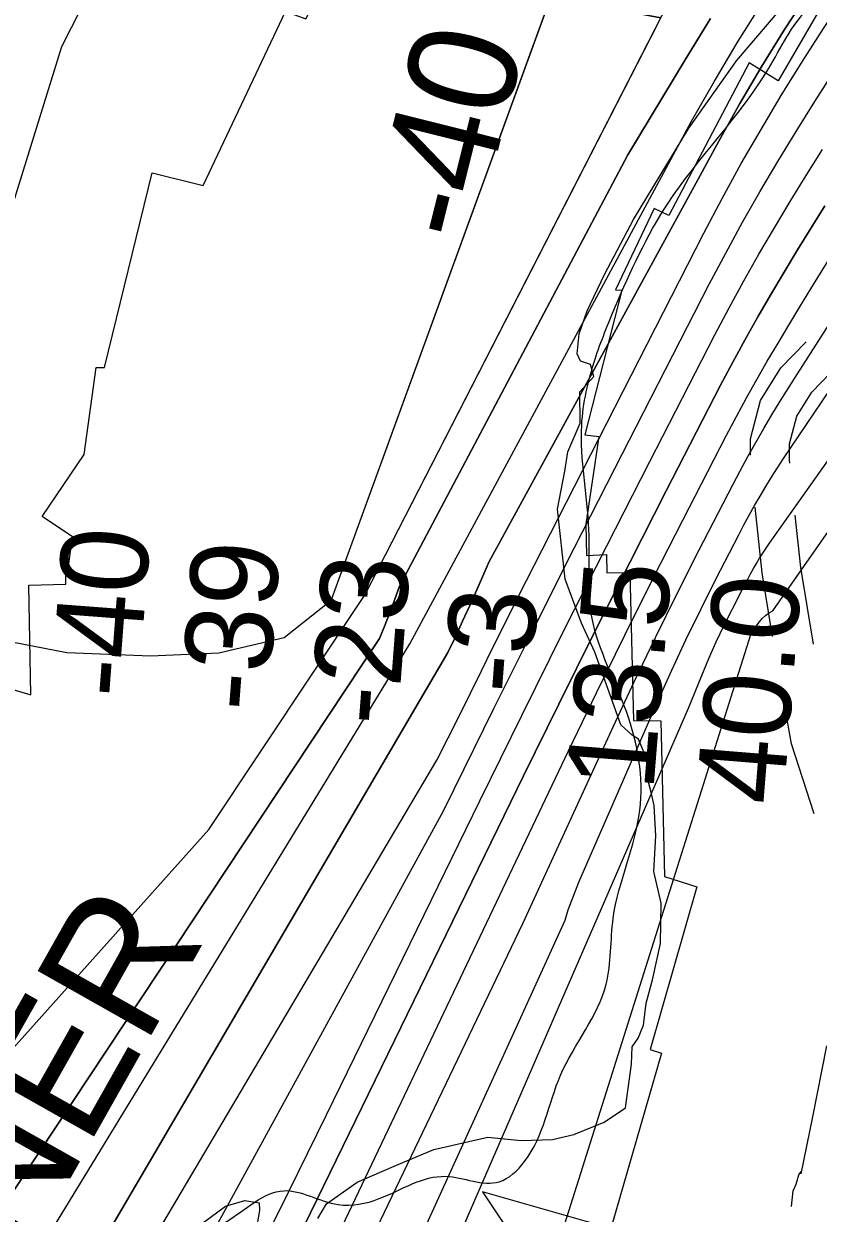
# Model space of a CAD drawing. Extents: x 3271442 to 3309282, y 752266 to 777610.
# Drawn here: x 3288016 to 3288625, y 760687 to 761598 of the extents above; entities that cross this region are included whole.
import ezdxf

# ---------------------------------------------------------------- set-up
doc = ezdxf.new("R2010")
doc.units = 0
for name, color, linetype in [('V-RIVR-EDGE', 7, 'Continuous'), ('V-RIVR-RANG', 7, 'Continuous'), ('V-ROAD-CNTR', 7, 'Continuous'), ('V-RRAP-FSHR', 7, 'Continuous'), ('V-RRAP-RVMT', 7, 'Continuous'), ('V-RRAP-RVMT-IDEN', 7, 'Continuous'), ('V-TOPO-DPTH', 7, 'Continuous'), ('V-TOPO-MAJR', 7, 'Continuous'), ('V-TOPO-MINR', 7, 'Continuous'), ('V-TOPO-MINR-IDEN', 7, 'Continuous'), ('V-TOPO-WATR', 7, 'Continuous')]:
    doc.layers.add(name, color=color, linetype=linetype)

msp = doc.modelspace()

# ---------------------------------------------------------------- linework, layer by layer
at = {"layer": 'V-RIVR-EDGE'}
for points in [[(3288447.55, 761378.15), (3288460.66, 761405.94), (3288482.93, 761448.04), (3288525.27, 761517.92), (3288561.91, 761569.56), (3288609.43, 761625.52)], [(3288241.1, 760682.74), (3288247.65, 760694.02), (3288271.16, 760710.48), (3288301.19, 760723.45), (3288329.9, 760735.55), (3288371.22, 760745.01), (3288396.86, 760742.34), (3288420.77, 760743.15), (3288437.3, 760747.02), (3288460.36, 760756.53), (3288476.9, 760767.35), (3288481.33, 760800.81), (3288481.8, 760814.29), (3288486.6, 760820.79), (3288490.54, 760830.78), (3288492.75, 760847.73), (3288497.58, 760865.54), (3288503.73, 760893.34), (3288504.24, 760924.2), (3288498.65, 760948.56), (3288500.02, 760975.94), (3288498.78, 760998.98), (3288496.2, 761010.29), (3288493.61, 761019.86), (3288494.08, 761032.03), (3288486.73, 761049.87), (3288481.96, 761052.92), (3288473.28, 761060.77), (3288453.43, 761116.46), (3288443.05, 761138.65), (3288430.53, 761172.59), (3288424.57, 761226.07), (3288430.3, 761255.18), (3288432.51, 761269.95), (3288442.12, 761292.1), (3288441.75, 761316), (3288452.64, 761327.71), (3288450.06, 761336.85), (3288442.24, 761339.48), (3288439.65, 761345.13), (3288441.42, 761360.34), (3288447.55, 761378.15)], [(3288130.21, 760662.58), (3288170.27, 760692.04), (3288185.06, 760696.35), (3288195.92, 760694.59), (3288196.34, 760688.93), (3288192.81, 760668.51)]]:
    msp.add_lwpolyline(points, dxfattribs=at)
at = {"layer": 'V-ROAD-CNTR'}
for points in [[(3288572.54, 761267.49), (3288572.59, 761280), (3288580.22, 761309.33), (3288595.95, 761334.35), (3288615.18, 761354.2)], [(3288602.75, 761261.37), (3288602.52, 761263.53), (3288602.58, 761276.1), (3288608.09, 761297.29), (3288619.68, 761315.73), (3288648.61, 761345.59)], [(3288589.61, 761128.64), (3288581.48, 761177.34), (3288576.15, 761227.68)], [(3288621.03, 761122.63), (3288611.22, 761181.39), (3288606.96, 761221.59)], [(3288621.34, 760992.61), (3288604.1, 761046.35), (3288596.29, 761089.2)], [(3288611.41, 760716.82), (3288620.42, 760760.57), (3288631.06, 760814.87)], [(3288604.06, 760691.85), (3288605.21, 760703.88), (3288607.53, 760709.03), (3288608.4, 760711.59), (3288609.74, 760716.2), (3288611.37, 760718.69)]]:
    msp.add_lwpolyline(points, dxfattribs=at)
at = {"layer": 'V-RRAP-FSHR'}
msp.add_spline([(3288024.63, 760323.97), (3288039.3, 760373.12), (3288065.44, 760447.36), (3288088.5, 760530.02), (3288126.81, 760603.55), (3288137.93, 760646.78), (3288150.99, 760667.86), (3288170.61, 760680.17), (3288214.86, 760704), (3288256.53, 760693.32), (3288288.02, 760697.88), (3288338.99, 760715), (3288379.97, 760710.81), (3288399.44, 760726.31), (3288427.1, 760792.56), (3288462.02, 760862.23), (3288467.43, 760912.73), (3288487.79, 760995.52), (3288477.56, 761070.97), (3288451.29, 761142.34), (3288448.83, 761210.37), (3288443.25, 761290.39), (3288453.5, 761340.99), (3288468.99, 761381.1), (3288508.98, 761459.84), (3288586.39, 761563.48), (3288616.8, 761609.67), (3288678.43, 761644.56), (3288740.06, 761679.44), (3288795.46, 761719.02), (3288838.61, 761790.36), (3288890.24, 761863.5)], degree=3, dxfattribs=at)
at = {"layer": 'V-RRAP-RVMT'}
for points in [[(3288047.91, 761168.75), (3288047.63, 761183.56), (3288050.01, 761184.17), (3288052.93, 761204.97), (3288029.62, 761220.55), (3288061.78, 761268.08), (3288071.12, 761334.61), (3288077.38, 761334.68), (3288113.96, 761483.64), (3288153.2, 761474.08), (3288216.08, 761607.39), (3288231.66, 761601.64), (3288299.01, 761732.39), (3288303.07, 761730.39), (3288378.07, 761859.59), (3288404.93, 761842.28), (3288478.05, 761968.95), (3288490.91, 761961.39), (3288564.39, 762088.36), (3288581.34, 762077.72), (3288654.82, 762203.99)], [(3289090.33, 762108.87), (3289016.46, 761984.19), (3288991.86, 761997.73), (3288977.5, 761981.67), (3288914.59, 761873.35), (3288889.01, 761888.63), (3288815.29, 761762.18), (3288792.96, 761775.53), (3288720.4, 761650.05), (3288666.66, 761679.67), (3288593.77, 761554.36), (3288571.56, 761568.06), (3288510.09, 761451.04), (3288498.72, 761456.41), (3288469.1, 761394.2), (3288473.95, 761394), (3288445.57, 761283.02), (3288456.34, 761281.88), (3288446.51, 761214.53), (3288446.97, 761190.48), (3288462.2, 761191.44), (3288462.46, 761177.3)], [(3288462.46, 761177.3), (3288480.11, 761177.51), (3288482.87, 761064.13), (3288503.81, 761064), (3288506.71, 760944.59), (3288531.46, 760936.86), (3288495.73, 760812.05), (3288504.42, 760809.36), (3288465.59, 760675.1), (3288367.13, 760703.2), (3288410.28, 760638.16)], [(3287405.23, 759886.02), (3287443.57, 760020.81), (3287460.11, 760016.42), (3287494.03, 760134.84), (3287492.61, 760135.21), (3287530.39, 760269.65), (3287551.7, 760263.93), (3287587.78, 760391.62), (3287592.82, 760390.19), (3287628.55, 760516.3), (3287648.53, 760510.74), (3287685, 760638.05), (3287782.33, 760610.6), (3287818.27, 760735.36), (3287841.66, 760728.59), (3287877.58, 760854.27), (3287882.41, 760853.2), (3287917.79, 760976.97), (3287953.93, 760967.05), (3287989.71, 761092.96), (3288021.11, 761083.88), (3288019.36, 761167.95), (3288047.91, 761168.75)]]:
    msp.add_lwpolyline(points, dxfattribs=at)
at = {"layer": 'V-TOPO-DPTH'}
for p, q in [((3288629.55, 761458.53), (3288619.09, 761441.64)), ((3288619.09, 761441.64), (3288608.7, 761424.71)), ((3288608.7, 761424.71), (3288598.43, 761407.7)), ((3288598.43, 761407.7), (3288588.23, 761390.65)), ((3288588.23, 761390.65), (3288578.25, 761373.47)), ((3288578.25, 761373.47), (3288568.48, 761356.18)), ((3288568.48, 761356.18), (3288559.02, 761338.72)), ((3288559.02, 761338.72), (3288549.76, 761321.14)), ((3288549.76, 761321.14), (3288508.08, 761240.22)), ((3288508.08, 761240.22), (3288480.3, 761185.85)), ((3288480.3, 761185.85), (3288452.76, 761131.37)), ((3288452.76, 761131.37), (3288425.59, 761076.7)), ((3288425.59, 761076.7), (3288398.66, 761021.91))]:
    msp.add_line(p, q, dxfattribs=at)
for points in [[(3287738.29, 760512.96), (3288157.38, 760980.59), (3288277.25, 761160.7), (3288623.48, 761835.79), (3288633.92, 761851.98), (3288644.26, 761868.24), (3289076.32, 762359.08)], [(3287924.79, 761194.92), (3288044.85, 761580.52), (3288154.96, 761797.02), (3288250.46, 761887.3), (3288286.32, 761937.24), (3288384.36, 762089.45), (3288463.32, 762232.18), (3288501.5, 762258.28), (3288522.94, 762258.23), (3288549.12, 762248.64), (3288563.33, 762217.64), (3288567.95, 762160.45), (3288529.25, 761922.34), (3288507.66, 761860.46), (3288419.53, 761618.52), (3288503.81, 761602.46)], [(3288549.12, 762248.64), (3288563.33, 762217.64), (3288567.95, 762160.45), (3288529.25, 761922.34), (3288507.66, 761860.46), (3288251.04, 761156), (3288215.24, 761127.51), (3288165.18, 761115.72), (3288112.77, 761113.47), (3288048.46, 761116.01), (3287998.46, 761125.66), (3287955.6, 761132.91), (3287934.21, 761152.02), (3287924.79, 761194.92), (3288044.85, 761580.52), (3288154.96, 761797.02), (3288250.46, 761887.3), (3288286.32, 761937.24), (3288384.36, 762089.45), (3288463.32, 762232.18), (3288501.5, 762258.28), (3288522.94, 762258.23), (3288549.12, 762248.64)], [(3288092.9, 760548.2), (3288337.36, 760994.88), (3288345.58, 761011.67), (3288375.95, 761073.3), (3288406.55, 761134.8), (3288437.5, 761196.14), (3288468.69, 761257.35), (3288541.05, 761398.43), (3288553.61, 761422.27), (3288566.49, 761445.94), (3288579.88, 761469.32), (3288593.6, 761492.52), (3288607.68, 761515.51), (3288621.93, 761538.39), (3288636.42, 761561.12), (3288651.06, 761583.76), (3288782.4, 761784.41)], [(3288092.9, 760548.2), (3288337.36, 760994.88), (3288345.58, 761011.67), (3288375.95, 761073.3), (3288406.55, 761134.8), (3288437.5, 761196.14), (3288468.69, 761257.35), (3288541.05, 761398.43), (3288553.61, 761422.27), (3288566.49, 761445.94), (3288579.88, 761469.32), (3288593.6, 761492.52), (3288607.68, 761515.51), (3288621.93, 761538.39), (3288636.42, 761561.12), (3288651.06, 761583.76), (3288782.4, 761784.41)], [(3288051.29, 760622.7), (3288340.7, 761116.32), (3288346.39, 761128.25), (3288351.99, 761140.23), (3288357.43, 761152.28), (3288362.78, 761164.37), (3288370.66, 761182.53), (3288372.1, 761185.51), (3288373.68, 761188.41), (3288532.45, 761478.8), (3288548.23, 761507.97), (3288564.48, 761536.87), (3288581.41, 761565.38), (3288598.79, 761593.63), (3288616.74, 761621.52)], [(3288616.74, 761621.52), (3288598.79, 761593.63), (3288581.41, 761565.38), (3288564.48, 761536.87), (3288548.23, 761507.97), (3288532.45, 761478.8), (3288373.68, 761188.41), (3288372.1, 761185.51), (3288370.66, 761182.53), (3288362.78, 761164.37), (3288357.43, 761152.28), (3288351.99, 761140.23), (3288346.39, 761128.25), (3288340.7, 761116.32), (3288051.29, 760622.7)], [(3288501.25, 761597.47), (3288503.81, 761602.46), (3288419.53, 761618.52), (3288416.57, 761610.4), (3288251.04, 761156), (3288215.24, 761127.51), (3288165.18, 761115.72), (3288112.77, 761113.47), (3288048.46, 761116.01), (3287998.46, 761125.66)], [(3287737.65, 760511.18), (3287738.29, 760512.96), (3288157.38, 760980.59), (3288277.25, 761160.7), (3288501.25, 761597.47)], [(3288542.04, 761601.95), (3288522.55, 761570.32), (3288478.73, 761497.52), (3288303.46, 761167.2), (3288299.88, 761157.06), (3288296.18, 761146.96), (3288292.3, 761136.93), (3288288.31, 761126.95), (3287896.68, 760536.42)], [(3288542.04, 761601.95), (3288522.55, 761570.32), (3288478.73, 761497.52), (3288303.46, 761167.2), (3288299.88, 761157.06), (3288296.18, 761146.96), (3288292.3, 761136.93), (3288288.31, 761126.95), (3287896.68, 760536.42)], [(3288398.66, 761021.91), (3288156.23, 760524.49), (3288155.88, 760523.76)]]:
    msp.add_lwpolyline(points, dxfattribs=at)
at = {"layer": 'V-TOPO-MAJR'}
for p, q in [((3288598.04, 761264.83), (3288667.72, 761368.6)), ((3288588.8, 761250.63), (3288593.38, 761257.76)), ((3288593.38, 761257.76), (3288598.04, 761264.83)), ((3288584.36, 761243.43), (3288588.8, 761250.63)), ((3288580, 761236.17), (3288584.36, 761243.43)), ((3288571.61, 761221.45), (3288575.76, 761228.83)), ((3288575.76, 761228.83), (3288580, 761236.17)), ((3288567.59, 761214), (3288571.61, 761221.45)), ((3288563.64, 761206.51), (3288567.59, 761214)), ((3288546.07, 761172.39), (3288563.64, 761206.51)), ((3288534.46, 761149.32), (3288546.07, 761172.39)), ((3288523.14, 761126.11), (3288534.46, 761149.32)), ((3288512.27, 761102.68), (3288523.14, 761126.11)), ((3288501.69, 761079.12), (3288512.27, 761102.68)), ((3288441, 760940.34), (3288501.69, 761079.12)), ((3288432.98, 760919.15), (3288441, 760940.34)), ((3288430.57, 760911.19), (3288432.98, 760919.15))]:
    msp.add_line(p, q, dxfattribs=at)
msp.add_lwpolyline([(3288069.72, 759951.08), (3288256.63, 760529.5), (3288430.57, 760911.19)], dxfattribs=at)
at = {"layer": 'V-TOPO-MINR'}
for p, q in [((3288589.79, 761148.28), (3289028.4, 761776.55)), ((3288609.02, 761230.77), (3288989.32, 761770.72)), ((3288618.84, 761394.82), (3288848.48, 761768.93)), ((3288608.55, 761329.77), (3288749.37, 761549.64)), ((3288615.33, 761481.81), (3288627.75, 761501.72)), ((3288603.07, 761461.79), (3288615.33, 761481.81)), ((3288590.93, 761441.71), (3288603.07, 761461.79)), ((3288619.09, 761441.64), (3288629.55, 761458.53)), ((3288579.07, 761421.46), (3288590.93, 761441.71)), ((3288608.7, 761424.71), (3288619.09, 761441.64)), ((3288567.47, 761401.07), (3288579.07, 761421.46)), ((3288598.43, 761407.7), (3288608.7, 761424.71)), ((3288588.23, 761390.65), (3288598.43, 761407.7)), ((3288556.28, 761380.45), (3288567.47, 761401.07)), ((3288610.42, 761381.01), (3288618.84, 761394.82)), ((3288578.25, 761373.47), (3288588.23, 761390.65)), ((3288545.34, 761359.69), (3288556.28, 761380.45)), ((3288602.05, 761367.18), (3288610.42, 761381.01)), ((3288568.48, 761356.18), (3288578.25, 761373.47)), ((3288593.76, 761353.29), (3288602.05, 761367.18)), ((3288495.44, 761262.66), (3288545.34, 761359.69)), ((3288559.02, 761338.72), (3288568.48, 761356.18)), ((3288585.51, 761339.38), (3288593.76, 761353.29)), ((3288549.76, 761321.14), (3288559.02, 761338.72)), ((3288577.43, 761325.37), (3288585.51, 761339.38)), ((3288601.96, 761319.36), (3288608.55, 761329.77)), ((3288508.08, 761240.22), (3288549.76, 761321.14)), ((3288569.51, 761311.28), (3288577.43, 761325.37)), ((3288561.82, 761297.06), (3288569.51, 761311.28)), ((3288595.45, 761308.9), (3288601.96, 761319.36)), ((3288589.07, 761298.36), (3288595.45, 761308.9)), ((3288554.29, 761282.75), (3288561.82, 761297.06)), ((3288582.76, 761287.78), (3288589.07, 761298.36)), ((3288576.6, 761277.11), (3288582.76, 761287.78)), ((3288520.74, 761217.63), (3288554.29, 761282.75)), ((3288570.56, 761266.37), (3288576.6, 761277.11)), ((3288564.7, 761255.53), (3288570.56, 761266.37)), ((3288462.41, 761197.92), (3288495.44, 761262.66)), ((3288558.97, 761244.62), (3288564.7, 761255.53)), ((3288480.3, 761185.85), (3288508.08, 761240.22)), ((3288533.4, 761195.01), (3288558.97, 761244.62)), ((3288587.27, 761200.08), (3288609.02, 761230.77)), ((3288498.35, 761173.68), (3288520.74, 761217.63)), ((3288429.64, 761133.05), (3288462.41, 761197.92)), ((3288516.42, 761161.49), (3288533.4, 761195.01)), ((3288579.63, 761188.52), (3288582.09, 761192.43)), ((3288582.09, 761192.43), (3288584.65, 761196.27)), ((3288584.65, 761196.27), (3288587.27, 761200.08)), ((3288452.76, 761131.37), (3288480.3, 761185.85)), ((3288574.93, 761180.56), (3288577.24, 761184.56)), ((3288577.24, 761184.56), (3288579.63, 761188.52)), ((3288570.47, 761172.47), (3288572.67, 761176.53)), ((3288572.67, 761176.53), (3288574.93, 761180.56)), ((3288476.24, 761129.59), (3288498.35, 761173.68)), ((3288558.73, 761149.78), (3288568.32, 761168.38)), ((3288568.32, 761168.38), (3288570.47, 761172.47)), ((3288499.73, 761127.83), (3288516.42, 761161.49)), ((3288552.45, 761137.17), (3288558.73, 761149.78)), ((3288586.83, 761146.6), (3288589.79, 761148.28)), ((3288576.19, 761135.51), (3288579.41, 761139.8)), ((3288579.41, 761139.8), (3288581.65, 761142.36)), ((3288581.65, 761142.36), (3288584.09, 761144.67)), ((3288584.09, 761144.67), (3288586.83, 761146.6)), ((3288397.28, 761067.98), (3288429.64, 761133.05)), ((3288425.59, 761076.7), (3288452.76, 761131.37)), ((3288454.54, 761085.31), (3288476.24, 761129.59)), ((3288546.4, 761124.46), (3288552.45, 761137.17)), ((3288572.89, 761130.05), (3288573, 761130.26)), ((3288573, 761130.26), (3288573.35, 761130.94)), ((3288573.35, 761130.94), (3288573.72, 761131.62)), ((3288573.72, 761131.62), (3288574.1, 761132.29)), ((3288574.1, 761132.29), (3288574.48, 761132.96)), ((3288574.48, 761132.96), (3288574.88, 761133.61)), ((3288574.88, 761133.61), (3288575.3, 761134.26)), ((3288575.3, 761134.26), (3288575.74, 761134.89)), ((3288575.74, 761134.89), (3288576.19, 761135.51)), ((3288483.51, 761093.94), (3288499.73, 761127.83)), ((3288540.69, 761111.59), (3288546.4, 761124.46)), ((3288535.21, 761098.61), (3288540.69, 761111.59)), ((3288467.58, 761059.91), (3288483.51, 761093.94)), ((3288525.1, 761073.74), (3288535.21, 761098.61)), ((3288433.12, 761040.88), (3288454.54, 761085.31)), ((3288398.66, 761021.91), (3288425.59, 761076.7)), ((3288365.19, 761002.77), (3288397.28, 761067.98)), ((3288398.28, 760909.12), (3288467.58, 761059.91)), ((3288235.95, 760627.06), (3288433.12, 761040.88)), ((3288247.67, 760762.06), (3288365.19, 761002.77)), ((3288233.16, 760732.47), (3288247.67, 760762.06)), ((3288218.6, 760702.92), (3288233.16, 760732.47)), ((3288203.95, 760673.41), (3288218.6, 760702.92))]:
    msp.add_line(p, q, dxfattribs=at)
for points in [[(3287738.29, 760512.96), (3288157.38, 760980.59), (3288277.25, 761160.7), (3288623.48, 761835.79), (3288633.92, 761851.98), (3288644.26, 761868.24), (3289076.32, 762359.08)], [(3288032.97, 760667.03), (3288311.41, 761122.86), (3288527.51, 761523.25), (3288545.15, 761554.02), (3288563.25, 761584.51), (3288582.03, 761614.58), (3288601.26, 761644.39), (3288603.46, 761647.71), (3288622.15, 761675.49), (3288641.13, 761703.06), (3288660.55, 761730.33), (3288680.26, 761757.4), (3288715.9, 761805.55), (3288718.01, 761808.39), (3288720.12, 761811.22), (3288722.25, 761814.04), (3288724.38, 761816.86), (3288726.51, 761819.68), (3288728.64, 761822.5), (3289235.31, 762246.87)], [(3288051.29, 760622.7), (3288340.7, 761116.32), (3288346.39, 761128.25), (3288351.99, 761140.23), (3288357.43, 761152.28), (3288362.78, 761164.37), (3288370.66, 761182.53), (3288372.1, 761185.51), (3288373.68, 761188.41), (3288532.45, 761478.8), (3288548.23, 761507.97), (3288564.48, 761536.87), (3288581.41, 761565.38), (3288598.79, 761593.63), (3288616.74, 761621.52)], [(3288049.23, 760555.86), (3288332.21, 761033.71), (3288340.85, 761050.83), (3288349.45, 761067.97), (3288357.98, 761085.14), (3288366.46, 761102.34), (3288374.94, 761119.54), (3288383.48, 761136.7), (3288392.11, 761153.83), (3288400.79, 761170.92), (3288536.95, 761437.42), (3288551.04, 761464.22), (3288565.55, 761490.79), (3288580.68, 761517.01), (3288596.23, 761543), (3288612.25, 761568.7), (3288628.51, 761594.26), (3288645.1, 761619.59)], [(3287896.68, 760536.42), (3288288.31, 761126.95), (3288292.3, 761136.93), (3288296.18, 761146.96), (3288299.88, 761157.06), (3288303.46, 761167.2), (3288478.73, 761497.52), (3288522.55, 761570.32), (3288542.04, 761601.95)], [(3288319.71, 760026.73), (3288363.67, 760467.3), (3288572.89, 761130.05)], [(3288037.03, 759736), (3288280.41, 760510.39), (3288525.1, 761073.74)], [(3288155.88, 760523.76), (3288156.23, 760524.49), (3288398.66, 761021.91)], [(3288070.27, 760063.5), (3288244.87, 760589.08), (3288398.28, 760909.12)]]:
    msp.add_lwpolyline(points, dxfattribs=at)
msp.add_lwpolyline([(3287924.79, 761194.92), (3288044.85, 761580.52), (3288154.96, 761797.02), (3288250.46, 761887.3), (3288286.32, 761937.24), (3288384.36, 762089.45), (3288463.32, 762232.18), (3288501.5, 762258.28), (3288522.94, 762258.23), (3288549.12, 762248.64), (3288563.33, 762217.64), (3288567.95, 762160.45), (3288529.25, 761922.34), (3288507.66, 761860.46), (3288251.04, 761156), (3288215.24, 761127.51), (3288165.18, 761115.72), (3288112.77, 761113.47), (3288048.46, 761116.01), (3287998.46, 761125.66), (3287955.6, 761132.91), (3287934.21, 761152.02)], close=True, dxfattribs=at)
at = {"layer": 'V-TOPO-WATR'}
msp.add_lwpolyline([(3288092.9, 760548.2), (3288337.36, 760994.88), (3288345.58, 761011.67), (3288375.95, 761073.3), (3288406.55, 761134.8), (3288437.5, 761196.14), (3288468.69, 761257.35), (3288541.05, 761398.43), (3288553.61, 761422.27), (3288566.49, 761445.94), (3288579.88, 761469.32), (3288593.6, 761492.52), (3288607.68, 761515.51), (3288621.93, 761538.39), (3288636.42, 761561.12), (3288651.06, 761583.76), (3288782.4, 761784.41)], dxfattribs=at)

# ---------------------------------------------------------------- texts
at = {"layer": 'V-RIVR-RANG'}
for s, rotation, p in [('-40', 85.67275, (3288102.89, 761080.16)), ('-39', 85.67275, (3288202.38, 761069.74)), ('-23', 85.67275, (3288301.86, 761059.05)), ('13.5', 85.38833, (3288498.08, 761009.42)), ('40.0', 85.38833, (3288597.55, 760998.73)), ('-3', 85.67275, (3288403.98, 761083.35))]:
    msp.add_text(s, height=67, rotation=rotation, dxfattribs=at).set_placement(p)
at = {"layer": 'V-RRAP-RVMT-IDEN'}
msp.add_text('KNER', height=100, rotation=60.55479, dxfattribs=at).set_placement((3287972.77, 760574.19))
at = {"layer": 'V-TOPO-MINR-IDEN'}
msp.add_text('-40', height=83, rotation=75.94843, dxfattribs=at).set_placement((3288360.75, 761427.43))

doc.saveas('drawing.dxf')
